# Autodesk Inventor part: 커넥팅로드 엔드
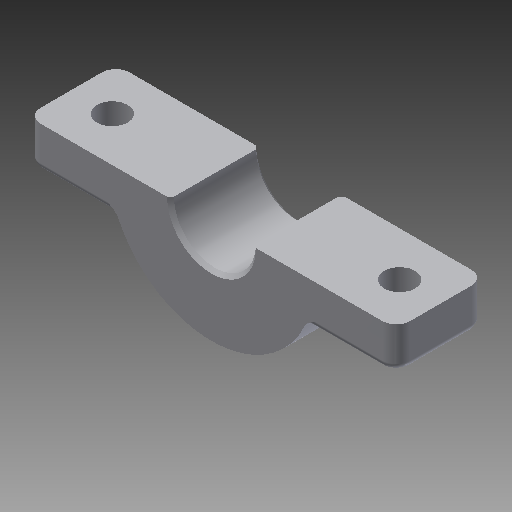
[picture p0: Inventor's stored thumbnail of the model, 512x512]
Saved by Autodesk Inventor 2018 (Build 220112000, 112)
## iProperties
Created: 2016-11
Part Number: 커넥팅로드 엔드
Material: 알루미늄 6061
Document SubType Name: Modeling
Designer: mduedu
Density: 2.71 g/cm^3
Mass: 15.0819 g
Surface Area: 26.6719 cm^2
Volume: 5.56529 cm^3
Appearance: 알루미늄 - 평지
Author: mduedu
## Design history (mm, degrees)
sketch "스케치1" dims "d0" = 30, "d3" = 15
  geometry: L1 (0, 0)-(0, 96); L2 (-5, 90.41)-(-10, 11.18); L3 (5, 90.41)-(10, 11.18); C1 r 6 at (0, 0); C2 r 4 at (0, 96); 3 further points
  constraints: 6 end point, 4 coincident, 2 centre point, 2 symmetric about line, 1 vertical, 6 other
  dimensions: "d1" = 12 diameter of C1; "d2" = 8 diameter of C2; "d4" = 96 distance of L1.start L1.end; "d6" = 10 distance from line of L1 L2.end; "d7" = 5 distance from line of L1 L2.start
extrude "돌출1" new body sketch "스케치1" stored distance "d8" = 13; taper "d9" = 0 deg
extrude "돌출2" join sketch "스케치1" stored distance "d10" = 32; taper "d11" = 0 deg
sketch "스케치2"
  geometry: L1 (5, 90.41)-(10, 11.18) reference; L2 (-5, 90.41)-(-10, 11.18) reference; A1 r 7.5 centre (0, 96) between (5, 90.41) and (-5, 90.41) reference; A2 r 15 centre (0, 0) between (10, 11.18) and (-10, 11.18) reference
extrude "돌출3" join sketch "스케치2" stored distance "d12" = 8; taper "d13" = 0 deg
sketch "스케치3"
  geometry: L1 (-2.732, 78.715)-(-6.171, 24.226); L2 (2.732, 78.715)-(6.171, 24.226); L3 (0, 78.5)-(0, 25); A1 r 17.5 centre (0, 96) between (-2.732, 78.715) and (2.732, 78.715); A2 r 25 centre (0, 0) between (6.171, 24.226) and (-6.171, 24.226); 9 further points; 2 other entities
  constraints: 6 end point, 6 point on circle, 2 centre point, 1 symmetric about line, 1 vertical alignment, 6 other
  dimensions: "d18" = 10 dimension on A1; "d19" = 10 dimension on A2; "d20" = 3 dimension on L1
extrude "돌출4" cut sketch "스케치3" distance "d21" = 2; taper "d22" = 0 deg
fillet "모깎기1" dims "d23" = 2
fillet "모깎기2" dims "d24" = 2
fillet "모깎기3" dims "d25" = 1
chamfer "모따기1" distance "d26" = 0.5; stored, may be unused: second distance "d27" = 2, angle "d28" = 45 deg
sketch "스케치4"
  geometry: L1 (-27, -6)-(-13.748, -6); L2 (27, -6)-(27, 6); L3 (27, 6)-(13.748, 6); L4 (-27, 6)-(-27, -6); L5 (-27, -6)-(27, 6); L6 (27, -6)-(-27, 6); L7 (-13.748, 6)-(-27, 6); L8 (13.748, 6)-(-13.748, 6); L9 (13.748, -6)-(27, -6); L10 (-13.748, -6)-(13.748, -6); A1 r 15 centre (0, 0) between (-13.748, 6) and (13.748, 6) reference; 1 further point
  constraints: 20 end point, 10 parallel, 4 point on circle, 3 horizontal, 3 perpendicular, 2 midpoint
  dimensions: "d29" = 54 distance of L1.start L2.start; "d31" = 12 distance of L2.start L2.end
extrude "돌출5" join sketch "스케치4" stored distance "d32" = 0; taper "d33" = 0 deg
fillet "모깎기4" dims "d34" = 2
fillet "모깎기5" dims "d35" = 1
fillet "모깎기6" dims "d36" = 1
sketch "스케치5"
  geometry: L1 (1, 0)-(1, 9) reference; L2 (-18.5, 20.5)-(-33.5, 20.5) reference; L3 (-33.5, -11.5)-(-18.5, -11.5) reference; L4 (-26, 20.5)-(-26, -11.5); 3 further points
  constraints: 2 end point, 2 midpoint, 1 horizontal alignment, 1 symmetric about line
  dimensions: "d37" = 6 distance from line of point (-5, 4.5) L1
feature "분할1"
sketch "스케치7"
  geometry: 2 further points
  constraints: 2 other
hole "구멍2" sketch "스케치7" at (-47, 4.5), (-5, 4.5) diameter "d45" = 4.5; stored, may be unused: countersink angle "d49" = 90 deg, drill point angle "d51" = 0 deg; dims "d46" = 6, "d47" = 4, "d48" = 2, "d50" = 8
node "솔리드1"
mirror "대칭1"
other parameters: "d16" = 4, "d17" = 4
